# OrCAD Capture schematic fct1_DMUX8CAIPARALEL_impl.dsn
size A
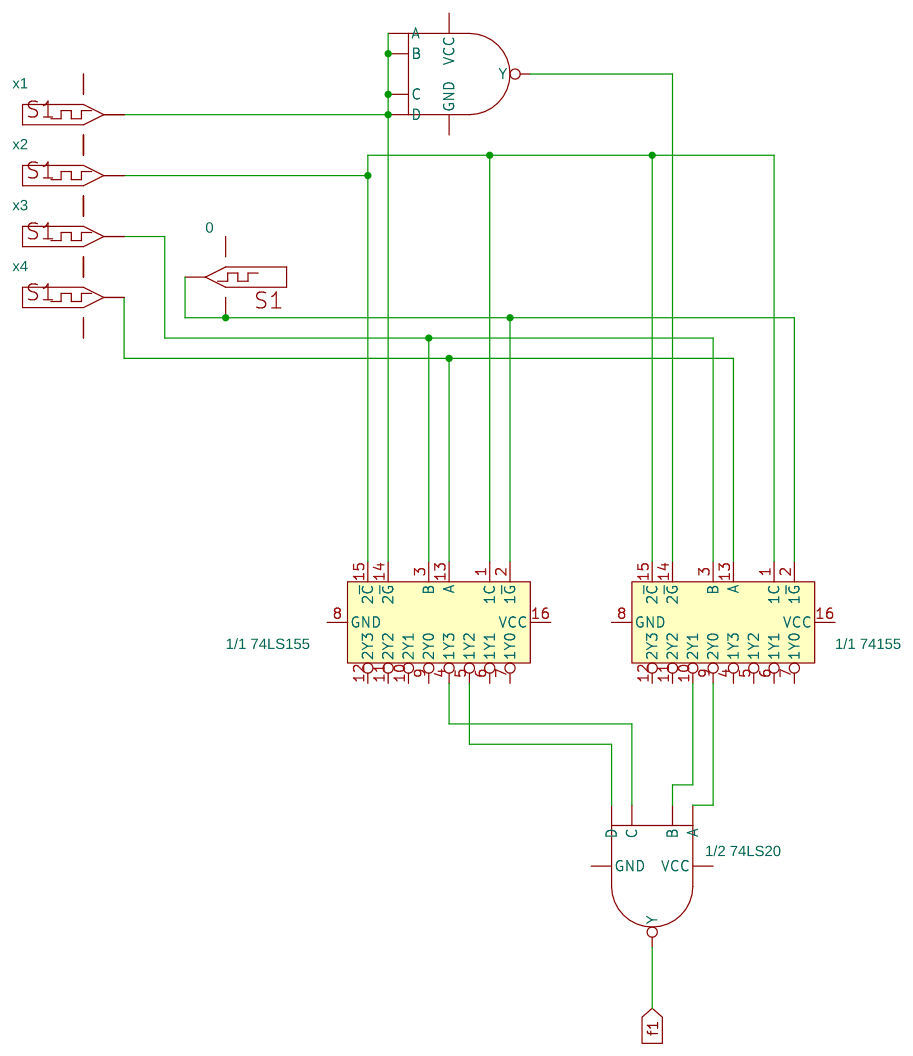
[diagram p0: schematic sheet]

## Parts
0  DigStim1
U3  1/1 74LS155  [DIP.100/16/W.300/L.900]
U4  1/1 74155  [DIP.100/16/W.300/L.900]
U7  1/2 74LS20  [DIP.100/14/W.300/L.800]  (sections A,B)
x1  DigStim1
x2  DigStim1
x3  DigStim1
x4  DigStim1

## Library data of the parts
0 x1-x4 = DigStim1
U3 U4 = 74155
U7 = 7420

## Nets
GND: 0.3(GND) U3.8(GND) U4.8(GND) U7.7(GND) x1.3(GND) x2.3(GND) x3.3(GND) x4.3(GND)
VCC: 0.2(VCC) U3.16(VCC) U4.16(VCC) U7.14(VCC) x1.2(VCC) x2.2(VCC) x3.2(VCC) x4.2(VCC)
f1: U7.6(Y)
N16886: U3.1(1C) U3.15(2~{C}) U4.1(1C) U4.15(2~{C}) x2.OUT
N17104: 0.OUT U3.2(1~{G}) U4.2(1~{G})
N17136: U3.13(A) U4.13(A) x4.OUT
N17158: U3.3(B) U4.3(B) x3.OUT
N17210: U3.14(2~{G}) U7.9(A) U7.10(B) U7.12(C) U7.13(D) x1.OUT
N17238: U4.14(2~{G}) U7.8(Y)
N17294: U3.5(1Y2) U7.5(D)
N17308: U3.4(1Y3) U7.4(C)
N17322: U4.9(2Y0) U7.1(A)
N17330: U4.10(2Y1) U7.2(B)

Not connected (* = marked no-connect by the designer): U3 6(1Y1) 7(1Y0) 9(2Y0) 10(2Y1) 11(2Y2) 12(2Y3); U4 4(1Y3) 5(1Y2) 6(1Y1) 7(1Y0) 11(2Y2) 12(2Y3)
